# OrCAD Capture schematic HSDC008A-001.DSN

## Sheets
1 5. Hardware Page: title: TUSB1044EVM-008; rev: A; note: HSDC008-001
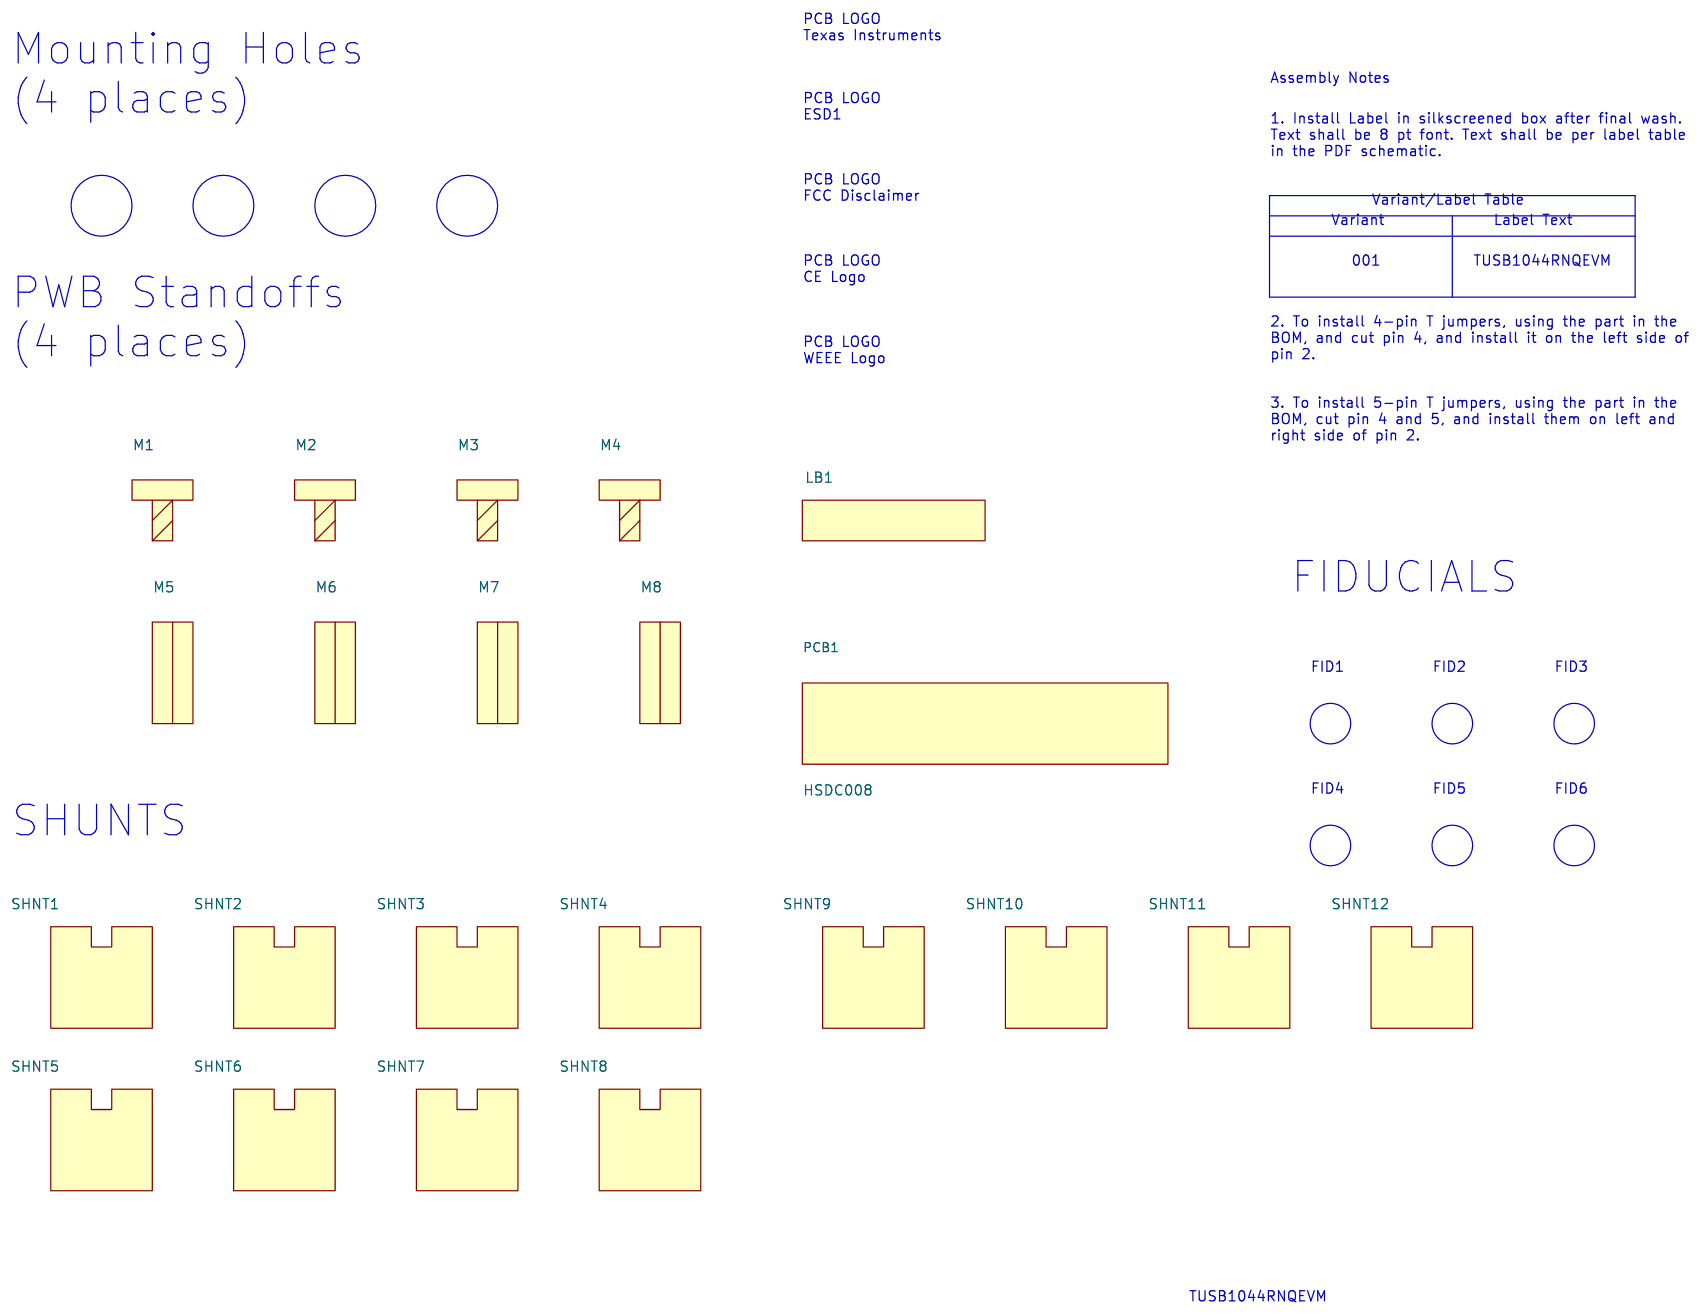
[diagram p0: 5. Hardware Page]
2 1. Block Diagram: title: TUSB1044RNQEVM
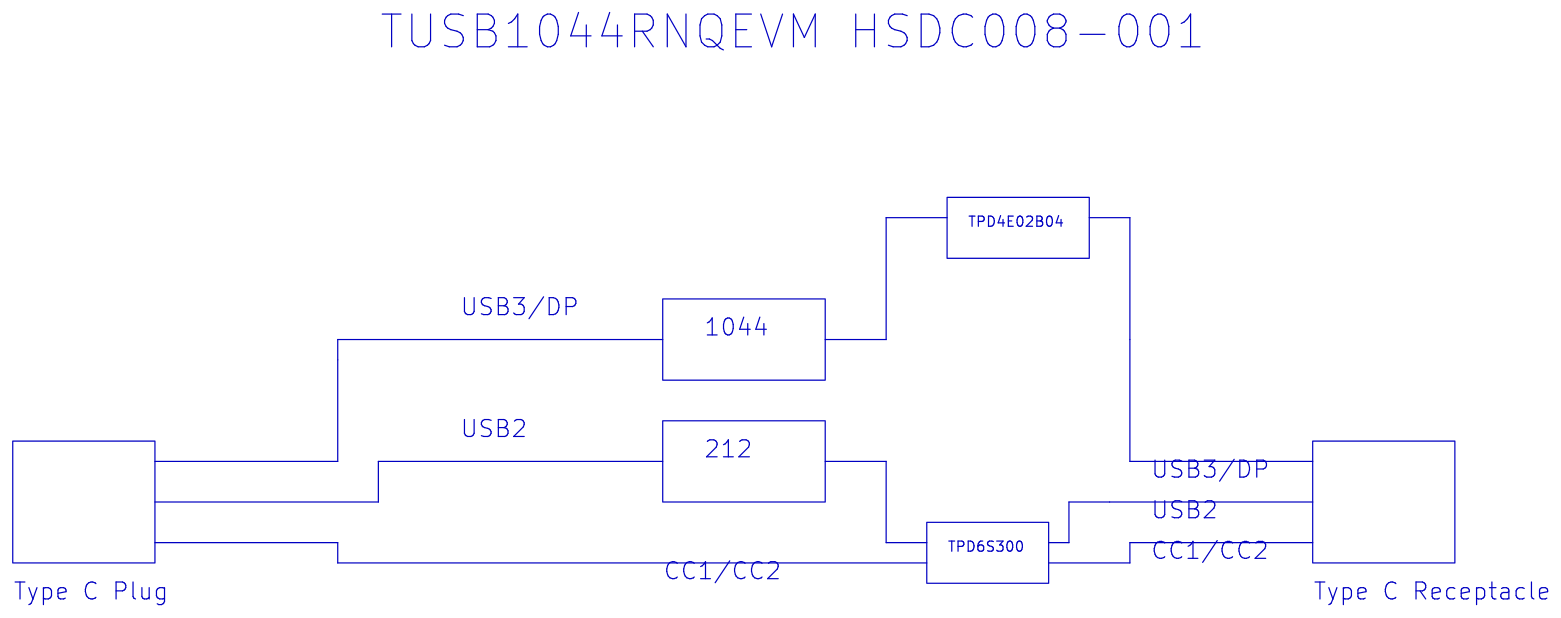
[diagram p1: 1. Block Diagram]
3 3. Configuration: size C; title: TUSB1044RNQEVM
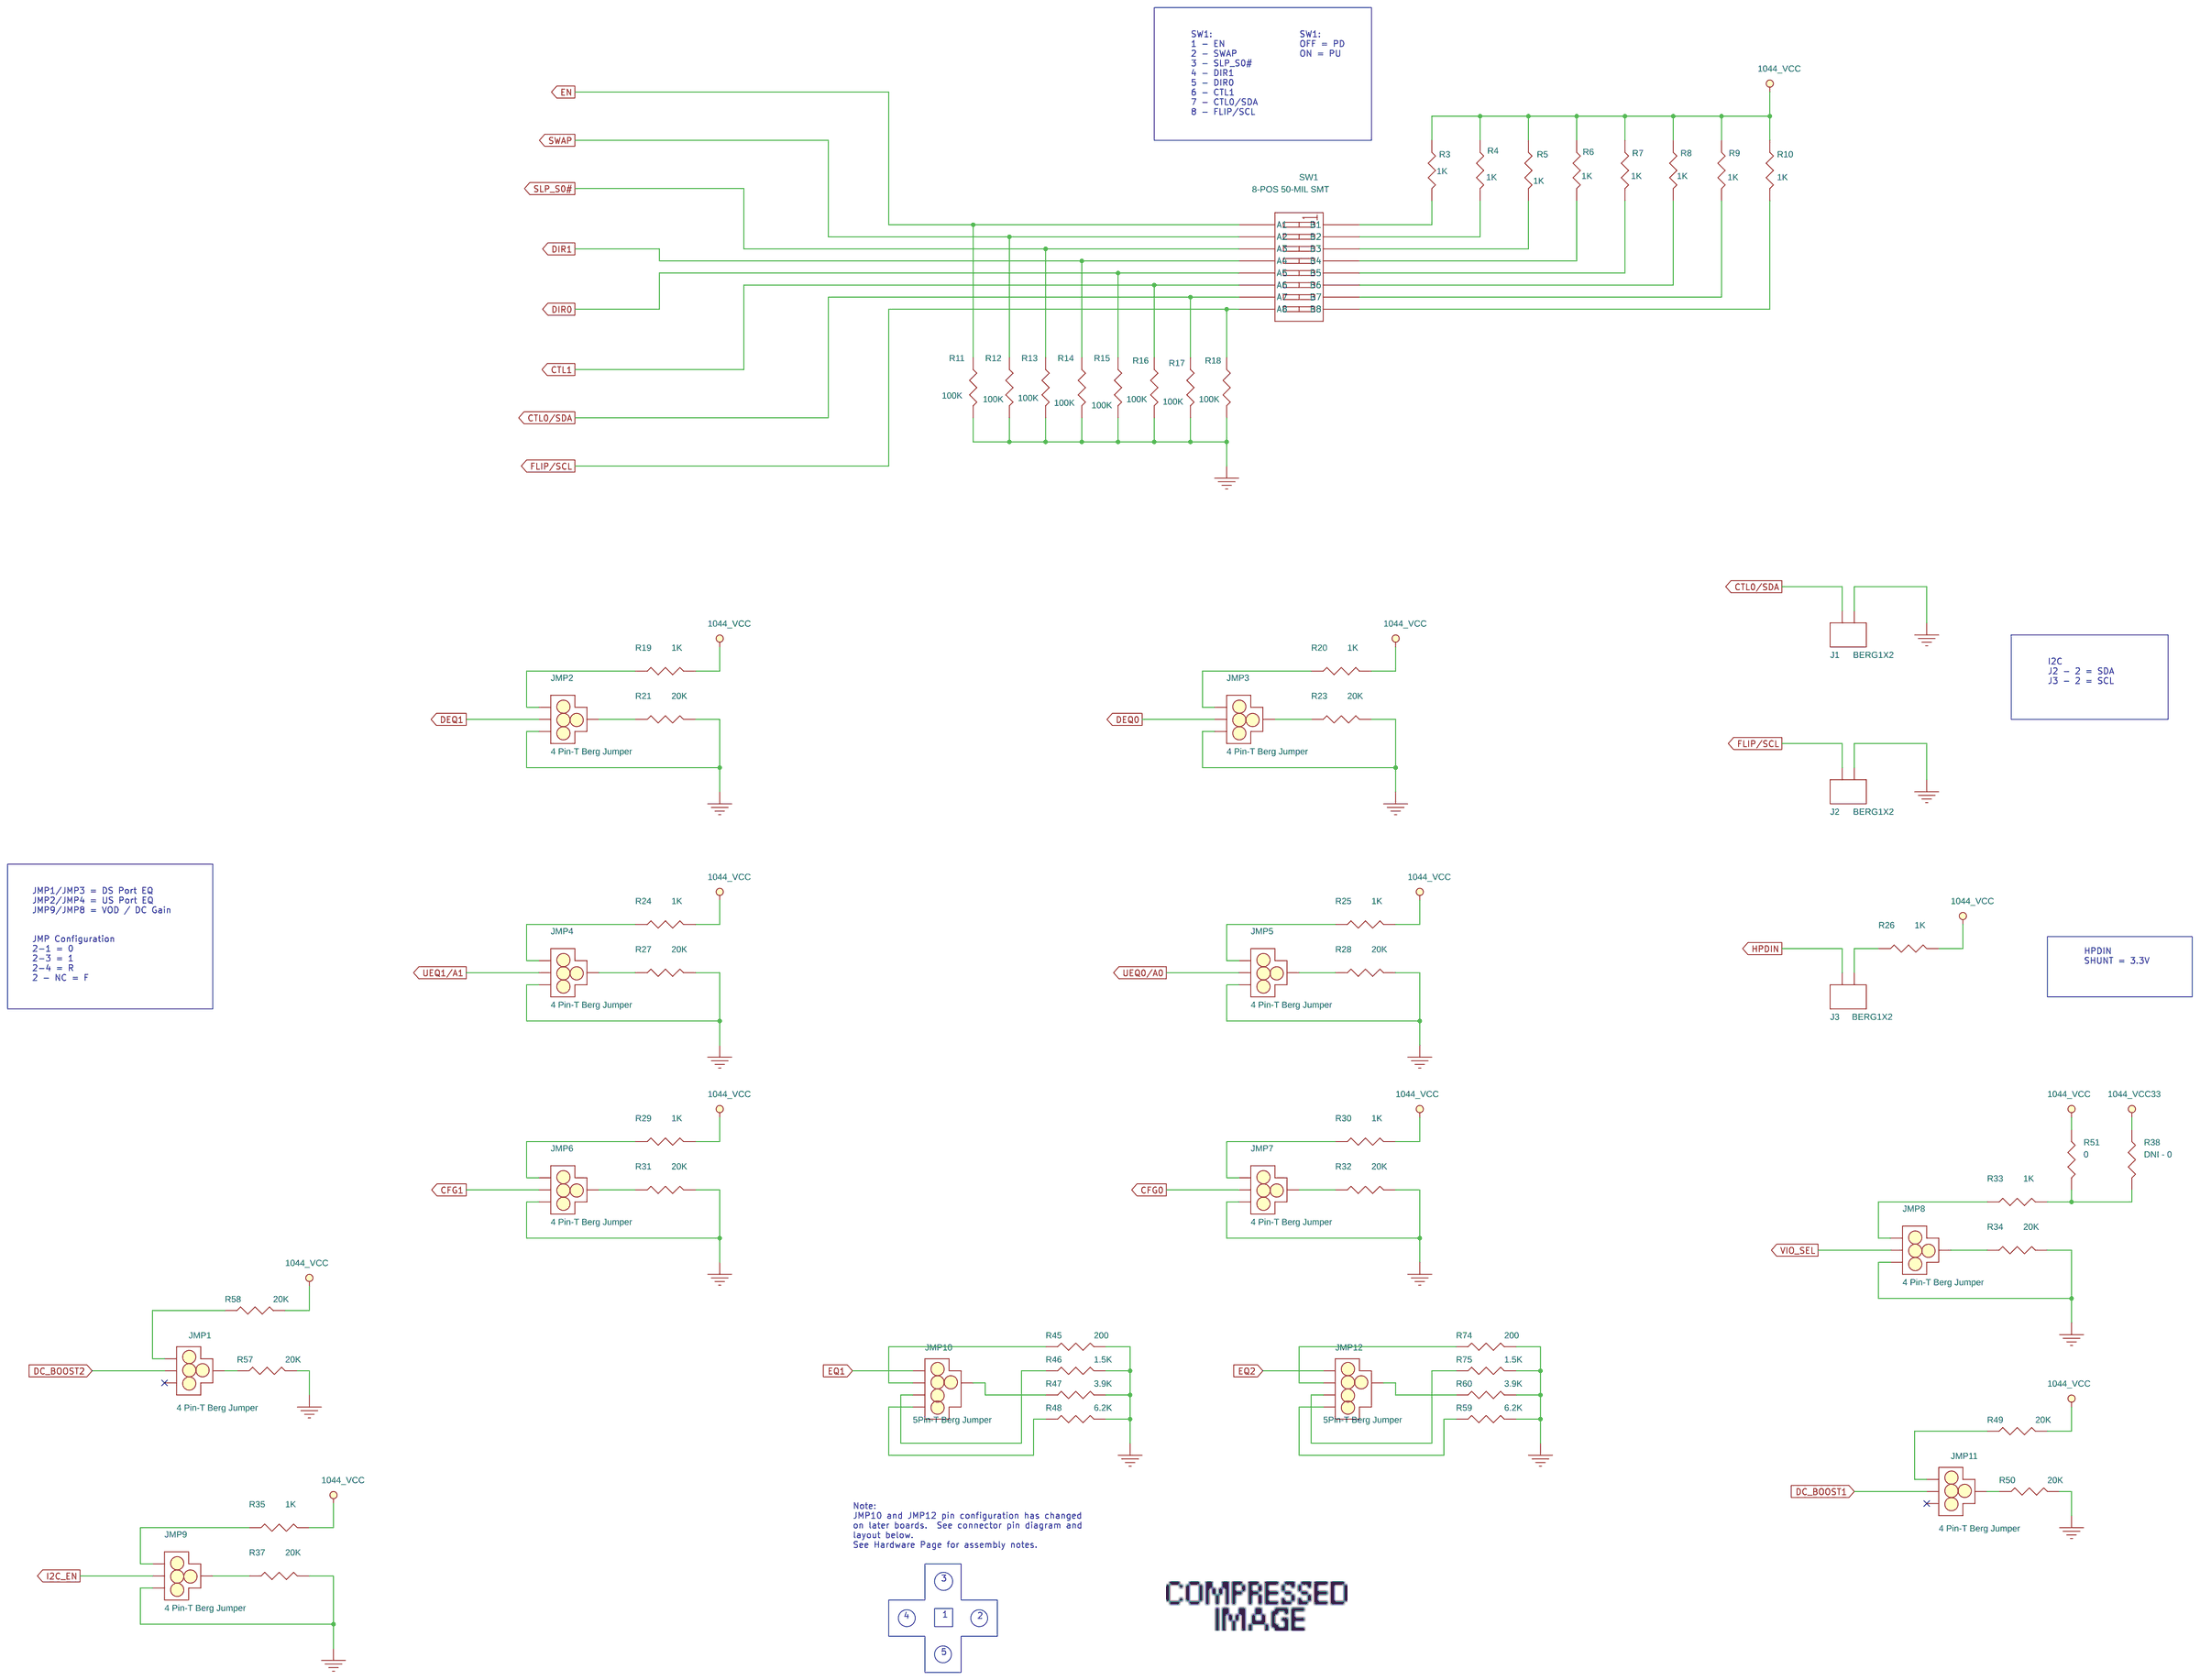
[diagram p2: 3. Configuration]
4 4. Power: size C; title: TUSB1044RNQEVM
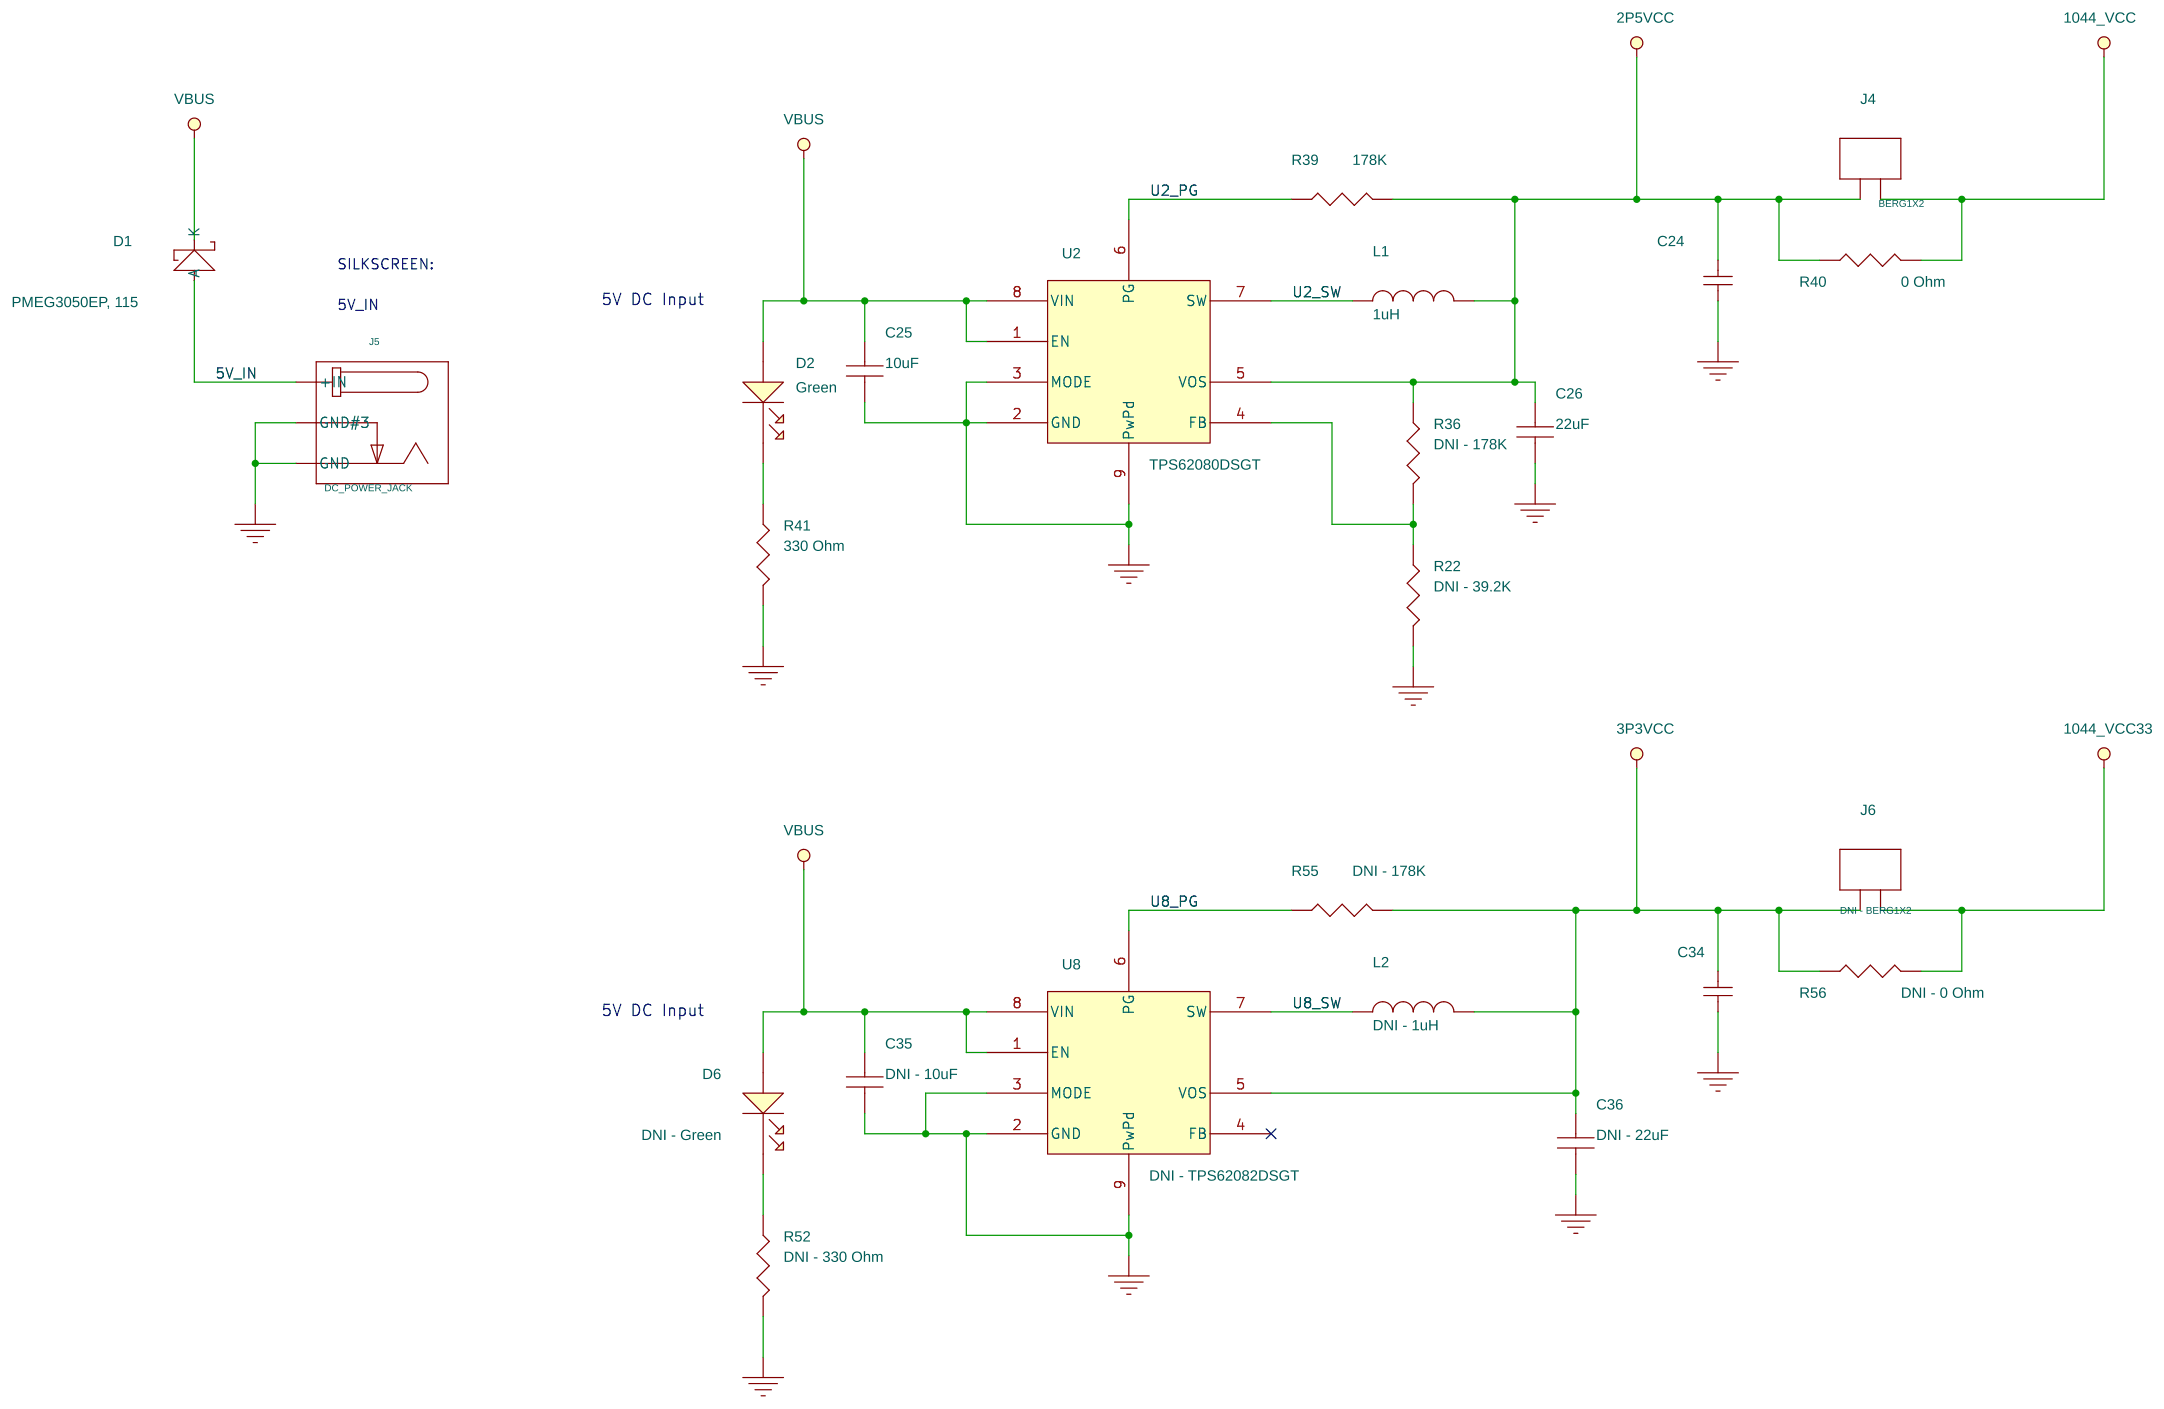
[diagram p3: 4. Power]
5 2. TUSB1044/46: size C; title: TUSB1044RNQEVM
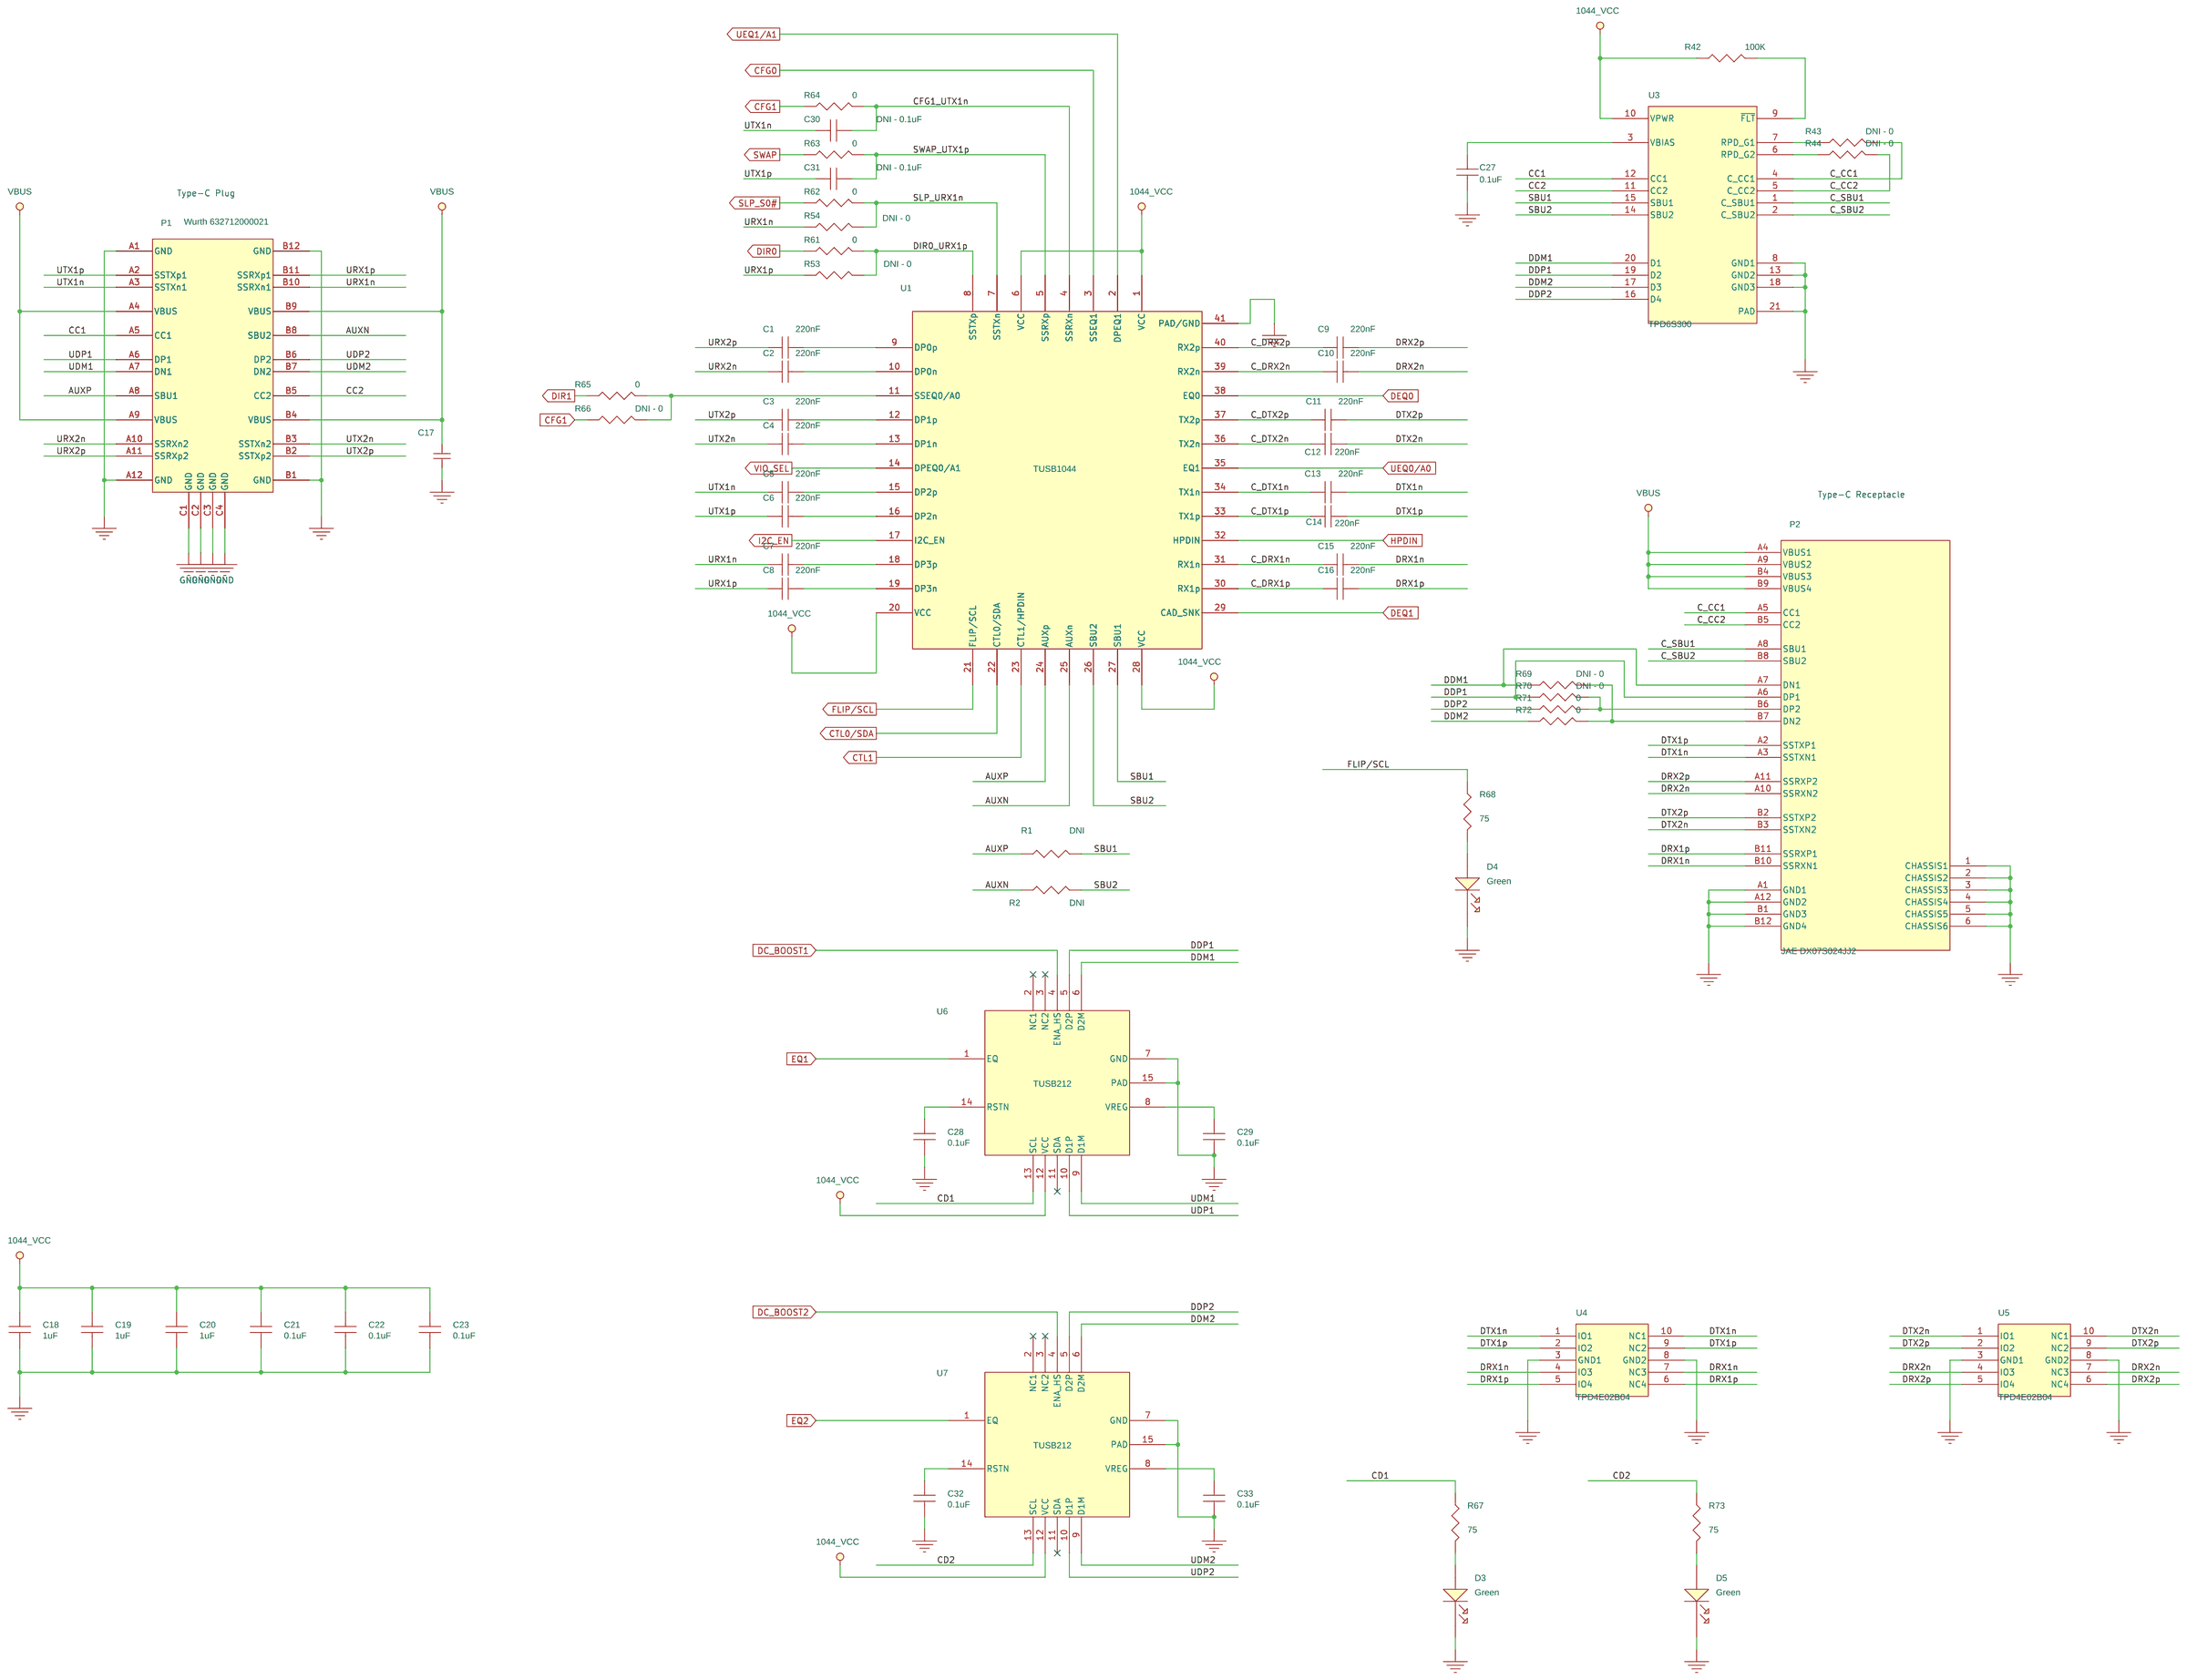
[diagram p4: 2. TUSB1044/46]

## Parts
sheet 2. TUSB1044/46
C1  220nF  [c0201]
C2  220nF  [c0201]
C3  220nF  [c0201]
C4  220nF  [c0201]
C5  220nF  [c0201]
C6  220nF  [c0201]
C7  220nF  [c0201]
C8  220nF  [c0201]
C9  220nF  [c0201]
C10  220nF  [c0201]
C11  220nF  [c0201]
C12  220nF  [c0201]
C13  220nF  [c0201]
C14  220nF  [c0201]
C15  220nF  [c0201]
C16  220nF  [c0201]
C17  10uF  [0805]
C18  1uF  [c0201]
C19  1uF  [c0201]
C20  1uF  [c0201]
C21  0.1uF  [c0201]
C22  0.1uF  [c0201]
C23  0.1uF  [c0201]
C27  0.1uF  [c0201]
C28  0.1uF  [c0201]
C29  0.1uF  [c0201]
C30  DNI - 0.1uF  [c0201]
C31  DNI - 0.1uF  [c0201]
C32  0.1uF  [c0201]
C33  0.1uF  [c0201]
D3  Green  [led0805]
D4  Green  [led0805]
D5  Green  [led0805]
P1  Wurth 632712000021  [usb-c_smrt_632_712_000_b6_b7]
P2  JAE DX07S024JJ2  [USB-C_SMRT_DX07S024JJ2]
R1  DNI  [r0402]
R2  DNI  [r0402]
R42  100K  [r0402]
R43  DNI - 0  [r0402]
R44  DNI - 0  [r0402]
R53  DNI - 0  [r0201]
R54  DNI - 0  [r0201]
R61  0  [r0201]
R62  0  [r0201]
R63  0  [r0201]
R64  0  [r0201]
R65  0  [r0201]
R66  DNI - 0  [r0201]
R67  75  [r0603]
R68  75  [r0603]
R69  DNI - 0  [r0201]
R70  DNI - 0  [r0201]
R71  0  [r0201]
R72  0  [r0201]
R73  75  [r0603]
U1  TUSB1044  [SKT_IRONWOOD_C14861_QFN-40]
U3  TPD6S300  [ruk0020b]
U4  TPD4E02B04  [dqa0010a]
U5  TPD4E02B04  [dqa0010a]
U6  TUSB212  [rgy_s-pvqfn-n14]
U7  TUSB212  [rgy_s-pvqfn-n14]
sheet 3. Configuration
J1  CON02  [HDR_THVT_1x2_100_M]
J2  CON02  [HDR_THVT_1x2_100_M]
J3  CON02  [HDR_THVT_1x2_100_M]
JMP1  4 Pin-T Berg Jumper  [berg2x3tee]
JMP2  4 Pin-T Berg Jumper  [berg2x3tee]
JMP3  4 Pin-T Berg Jumper  [berg2x3tee]
JMP4  4 Pin-T Berg Jumper  [berg2x3tee]
JMP5  4 Pin-T Berg Jumper  [berg2x3tee]
JMP6  4 Pin-T Berg Jumper  [berg2x3tee]
JMP7  4 Pin-T Berg Jumper  [berg2x3tee]
JMP8  4 Pin-T Berg Jumper  [berg2x3tee]
JMP9  4 Pin-T Berg Jumper  [berg2x3tee]
JMP10  5Pin-T Berg Jumper  [berg2x5tee]
JMP11  4 Pin-T Berg Jumper  [berg2x3tee]
JMP12  5Pin-T Berg Jumper  [berg2x5tee]
R3  1K  [r0402]
R4  1K  [r0402]
R5  1K  [r0402]
R6  1K  [r0402]
R7  1K  [r0402]
R8  1K  [r0402]
R9  1K  [r0402]
R10  1K  [r0402]
R11  100K  [r0402]
R12  100K  [r0402]
R13  100K  [r0402]
R14  100K  [r0402]
R15  100K  [r0402]
R16  100K  [r0402]
R17  100K  [r0402]
R18  100K  [r0402]
R19  1K  [r0402]
R20  1K  [r0402]
R21  20K  [r0402]
R23  20K  [r0402]
R24  1K  [r0402]
R25  1K  [r0402]
R26  1K  [r0402]
R27  20K  [r0402]
R28  20K  [r0402]
R29  1K  [r0402]
R30  1K  [r0402]
R31  20K  [r0402]
R32  20K  [r0402]
R33  1K  [r0402]
R34  20K  [r0402]
R35  1K  [r0402]
R37  20K  [r0402]
R38  DNI - 0  [r0402]
R45  200  [r0402]
R46  1.5K  [r0402]
R47  3.9K  [r0402]
R48  6.2K  [r0402]
R49  20K  [r0402]
R50  20K  [r0402]
R51  0  [r0402]
R57  20K  [r0402]
R58  20K  [r0402]
R59  6.2K  [r0402]
R60  3.9K  [r0402]
R74  200  [r0402]
R75  1.5K  [r0402]
SW1  8-POS 50-MIL SMT  [SW_SMVT_SPST_TDA08]
sheet 4. Power
C24  10uF  [0805]
C25  10uF  [0805]
C26  22uF  [0805]
C34  DNI - 10uF  [0805]
C35  DNI - 10uF  [0805]
C36  DNI - 22uF  [0805]
D1  SCHOTTKY  [diode_smb]
D2  Green  [led0805]
D6  DNI - Green  [led0805]
J4  CON02  [berg1x2]
J5  DC_PWR_JACK  [pj-202ah]
J6  CON02  [berg1x2]
L1  1uH  [IND_NR3015]
L2  DNI - 1uH  [IND_NR3015]
R22  DNI - 39.2K  [r0402]
R36  DNI - 178K  [r0402]
R39  178K  [r0402]
R40  0 Ohm  [r1206]
R41  330 Ohm  [r0603]
R52  DNI - 330 Ohm  [r0603]
R55  DNI - 178K  [r0402]
R56  DNI - 0 Ohm  [r1206]
U2  TPS62080DSGT  [dsg]
U8  DNI - TPS62082DSGT  [dsg]
sheet 5. Hardware Page
LB1  THD-47-478-10  [rectangle]
M1  NY PMS 440 005 PH  [screw]
M2  NY PMS 440 005 PH  [screw]
M3  NY PMS 440 005 PH  [screw]
M4  NY PMS 440 005 PH  [screw]
M5  1902E  [Standoff]
M6  1902E  [Standoff]
M7  1902E  [Standoff]
M8  1902E  [Standoff]
PCB1  HSDC008  [n/a]
SHNT1  QPC02SXGN-RC  [.1]
SHNT2  QPC02SXGN-RC  [.1]
SHNT3  QPC02SXGN-RC  [.1]
SHNT4  QPC02SXGN-RC  [.1]
SHNT5  QPC02SXGN-RC  [.1]
SHNT6  QPC02SXGN-RC  [.1]
SHNT7  QPC02SXGN-RC  [.1]
SHNT8  QPC02SXGN-RC  [.1]
SHNT9  QPC02SXGN-RC  [.1]
SHNT10  QPC02SXGN-RC  [.1]
SHNT11  QPC02SXGN-RC  [.1]
SHNT12  QPC02SXGN-RC  [.1]

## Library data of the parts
C1-C16 = cc0201
C17 C24 C34 = CAP: 6.3V Capacitor; $SEC: 1; ATIPartNo: 4210010600G; CDS_LIB: capacitor; DRAWING: @LIGHTNING_BOLT_NB_LIB.NOTE_BOOK(SCH_1):PAGE1; PHYS_PAGE: 1; ROT: 0; TOLERANCE: 10%; VER: 1; VOLTAGE: 6.3V; XY: (-9500,3550)
C18-C20 = cc0402: MFGP_N: GRM033R61A105ME15D
C21-C23 C27 C29 C33 = cc0402: MFGP_N: GRM033R62A104KE15D
C28 C30-C32 = cc0402
D2-D6 = Green_LED_2
P1 = Type_C_Plug_1
P2 = TypeC_JAE_TopMNT_1
R1-R21 R23-R35 R37 R39 R55 = r0402
R22 R36 R38 R42-R51 R53 R54 R57-R75 = R
U1 = TUSB1044RNQ_0
U3 = TPD8S300_0
U4 U5 = TPD4E02B04_0
U6 U7 = TUSB213_0
J1-J4 = CON02_2: Header; ATIPartNo: 6010014900G; CDS_LIB: connector; DEVICE_NAME: BERG1X2; DRAWING: @LIGHTNING_BOLT_NB_LIB.NOTE_BOOK(SCH_1):PAGE2; Digi-Key Part Number: 609-3507-ND; Manufacturer: FCI; Manufacturer Part Number: 68001-402HLF; Manufacturer's Part Number: 68001-402HLF; PHYS_PAGE: 2; ROT: 5; VER: 1; XY: (-6100,5150)
JMP1-JMP9 JMP11 = 4_Pin-T_Berg_Jumper
JMP10 JMP12 = 5Pin-T_Berg_Jumper
SW1 = SW_DIP-8_SM_0: Manuf: C&K(ITT-CANNON); Manuf PN: TDA08H0SK1R; Manufacturer: C&K(ITT-CANNON); Manufacturer Part Number: TDA08H0SK1R; Vendor: C&K (ITT-CANNON); Vendor Part Number: TDA08H0SK1R
C25 C26 C35 C36 = CAP_NP: 6.3V Capacitor
D1 = SCHOTTKY: Diode; $SEC: 1; CDS_LIB: diode; DEVICE_NAME: PMEG3050EP, 115; Digi-Key Part Number: 568-6753-2-ND; Manufacturer: NXP; Manufacturer Part Number: PMEG3050EP,115; Manufacturer's Part Number: PMEG3050EP,115; PHYS_PAGE: 1; ROT: 0; TOLERANCE: NA; VER: 1; VOLTAGE: 10V; XY: (-1750,3700)
J5 = 6140046600_DC_PWR_JACK: DC Power Jack; $SEC: 1; CDS_LIB: connector; DEVICE_NAME: DC_POWER_JACK; DRAWING: @LIGHTNING_BOLT_NB_LIB.NOTE_BOOK(SCH_1):PAGE2; Digi-Key Part Number: CP-202AH-ND; GroupName: COMMON; Manuf: CUI Inc.; Manuf PN: PJ-202AH; Manufacturer: CUI Inc.; Manufacturer Part Number: PJ-202AH; Manufacturer's Part Number: PJ-202AH; PHYS_PAGE: 2; ROT: 0; VER: 1; XY: (-4550,4450)
J6 = CON02_1: Header; ATIPartNo: 6010014900G; CDS_LIB: connector; DEVICE_NAME: DNI - BERG1X2; DRAWING: @LIGHTNING_BOLT_NB_LIB.NOTE_BOOK(SCH_1):PAGE2; Digi-Key Part Number: 609-3507-ND; Manufacturer: FCI; Manufacturer Part Number: 68001-402HLF; Manufacturer's Part Number: 68001-402HLF; PHYS_PAGE: 2; ROT: 5; VER: 1; XY: (-6100,5150)
L1 L2 = INDUCTOR: Inductor; CDS_LIB: Inductor; Digi-Key Part Number: 587-1647-1-ND; Manuf: Taiyo Yuden; Manuf PN: NR3015T1R0N; Manufacturer: Taiyo Yuden; Manufacturer Part Number: NR3015T1R0N; Manufacturer's Part Number: NR3015T1R0N
R40 R56 = r1206
R41 R52 = r0603
U2 U8 = TPS62082: DC/DC Converter; Digi-Key Part Number: 296-29647-1-ND; Manuf: Texas Instruments; Manuf PN: TPS62082DSGT; Manufacturer: Texas Instruments; Manufacturer Part Number: TPS62082DSGT; Manufacturer's Part Number: TPS62082DSGT
LB1 = Label
M1-M4 = Screw_40x.5_Nylon
M5-M8 = Standoff
PCB1 = PCB: Manufacturer: Any; Manufacturer Part Number: HSDC025
SHNT1-SHNT12 = Shunt

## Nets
5V_IN: D1.2(A) J5.1(+IN)
GND: C17.2(B) C18.2 C19.2 C20.2 C21.2 C22.2 C23.2 C24.2(B) C25.2 C26.2 C27.2 C28.2 C29.2 C32.2 C33.2 C34.2(B) C35.2 C36.2 D3.1(CATHODE) D4.1(CATHODE) D5.1(CATHODE) J1.1(P1) J2.1(P1) J5.2(GND) J5.3(GND#3) JMP2.1 JMP3.1 JMP4.1 JMP5.1 JMP6.1 JMP7.1 JMP8.1 JMP9.1 P1.A1(GND) P1.A12(GND) P1.B1(GND) P1.B12(GND) P1.C1(GND) P1.C2(GND) P1.C3(GND) P1.C4(GND) P2.1(CHASSIS1) P2.2(CHASSIS2) P2.3(CHASSIS3) P2.4(CHASSIS4) P2.5(CHASSIS5) P2.6(CHASSIS6) P2.A1(GND1) P2.A12(GND2) P2.B1(GND3) P2.B12(GND4) R11.2 R12.2 R13.2 R14.2 R15.2 R16.2 R17.2 R18.2 R21.2 R22.2 R23.2 R27.2 R28.2 R31.2 R32.2 R34.2 R37.2 R41.2 R45.2 R46.2 R47.2 R48.2 R50.2 R52.2 R57.2 R59.2 R60.2 R74.2 R75.2 U1.41(PAD/GND) U2.2(GND) U2.3(MODE) U2.9(PwPd) U3.8(GND1) U3.13(GND2) U3.18(GND3) U3.21(PAD) U4.3(GND1) U4.8(GND2) U5.3(GND1) U5.8(GND2) U6.7(GND) U6.15(PAD) U7.7(GND) U7.15(PAD) U8.2(GND) U8.3(MODE) U8.9(PwPd)
VBUS: C17.1(A) C25.1 C35.1 D1.1(K) D2.2(ANODE) D6.2(ANODE) P1.A4(VBUS) P1.A9(VBUS) P1.B4(VBUS) P1.B9(VBUS) P2.A4(VBUS1) P2.A9(VBUS2) P2.B4(VBUS3) P2.B9(VBUS4) U2.1(EN) U2.8(VIN) U8.1(EN) U8.8(VIN)
2P5VCC: C24.1(A) C26.1 J4.2(P2) L1.2 R36.1 R39.2 R40.1 U2.5(VOS)
3P3VCC: C34.1(A) C36.1 J6.1(P2) L2.2 R55.2 R56.1 U8.5(VOS)
1044_VCC: C18.1 C19.1 C20.1 C21.1 C22.1 C23.1 J4.1(P1) R3.1 R4.1 R5.1 R6.1 R7.1 R8.1 R9.1 R10.1 R19.2 R20.2 R24.2 R25.2 R26.2 R29.2 R30.2 R35.2 R40.2 R42.1 R49.2 R51.1 R58.2 U1.1(VCC) U1.6(VCC) U1.20(VCC) U1.28(VCC) U3.10(VPWR) U6.12(VCC) U7.12(VCC)
1044_VCC33: J6.2(P1) R38.1 R56.2
AUXN: P1.B8(SBU2) R2.1 U1.25(AUXn)
AUXP: P1.A8(SBU1) R1.1 U1.24(AUXp)
C_CC1: P2.A5(CC1) R43.2 U3.4(C_CC1)
C_CC2: P2.B5(CC2) R44.2 U3.5(C_CC2)
C_DRX1n: C15.1 U1.31(RX1n)
C_DRX1p: C16.1 U1.30(RX1p)
C_DRX2n: C10.1 U1.39(RX2n)
C_DRX2p: C9.1 U1.40(RX2p)
C_DTX1n: C13.1 U1.34(TX1n)
C_DTX1p: C14.1 U1.33(TX1p)
C_DTX2n: C12.1 U1.36(TX2n)
C_DTX2p: C11.1 U1.37(TX2p)
C_SBU1: P2.A8(SBU1) U3.1(C_SBU1)
C_SBU2: P2.B8(SBU2) U3.2(C_SBU2)
CC1: P1.A5(CC1) U3.12(CC1)
CC2: P1.B5(CC2) U3.11(CC2)
CD1: R67.1 U6.13(SCL)
CD2: R73.1 U7.13(SCL)
CFG0: JMP7.2 U1.3(SSEQ1)
CFG1: JMP6.2 R64.1 R66.1
CFG1_UTX1n: C30.2 R64.2 U1.4(SSRXn)
CTL0/SDA: J1.2(P2) R17.1 SW1.7(A7) U1.22(CTL0/SDA)
CTL1: R16.1 SW1.6(A6) U1.23(CTL1/HPDIN)
DC_BOOST1: JMP11.2 U6.4(ENA_HS)
DC_BOOST2: JMP1.2 U7.4(ENA_HS)
DDM1: P2.A7(DN1) R69.1 U3.20(D1) U6.6(D2M)
DDM2: R72.1 U3.17(D3) U7.6(D2M)
DDP1: P2.A6(DP1) R70.1 U3.19(D2) U6.5(D2P)
DDP2: R71.1 U3.16(D4) U7.5(D2P)
DEQ0: JMP3.2 U1.38(EQ0)
DEQ1: JMP2.2 U1.29(CAD_SNK)
DIR0: R15.1 R61.1 SW1.5(A5)
DIR0_URX1p: R53.2 R61.2 U1.8(SSTXp)
DIR1: R14.1 R65.1 SW1.4(A4)
DRX1n: C15.2 P2.B10(SSRXN1) U4.4(IO3) U4.7(NC3)
DRX1p: C16.2 P2.B11(SSRXP1) U4.5(IO4) U4.6(NC4)
DRX2n: C10.2 P2.A10(SSRXN2) U5.4(IO3) U5.7(NC3)
DRX2p: C9.2 P2.A11(SSRXP2) U5.5(IO4) U5.6(NC4)
DTX1n: C13.2 P2.A3(SSTXN1) U4.1(IO1) U4.10(NC1)
DTX1p: C14.2 P2.A2(SSTXP1) U4.2(IO2) U4.9(NC2)
DTX2n: C12.2 P2.B3(SSTXN2) U5.1(IO1) U5.10(NC1)
DTX2p: C11.2 P2.B2(SSTXP2) U5.2(IO2) U5.9(NC2)
EN: R11.1 SW1.1(A1)
EQ1: JMP10.1 U6.1(EQ)
EQ2: JMP12.1 U7.1(EQ)
FLIP/SCL: J2.2(P2) R18.1 R68.1 SW1.8(A8) U1.21(FLIP/SCL)
HPDIN: J3.2(P2) U1.32(HPDIN)
I2C_EN: JMP9.2 U1.17(I2C_EN)
SBU1: R1.2 U1.27(SBU1) U3.15(SBU1)
SBU2: R2.2 U1.26(SBU2) U3.14(SBU2)
SLP_S0#: R13.1 R62.1 SW1.3(A3)
SLP_URX1n: R54.2 R62.2 U1.7(SSTXn)
SWAP: R12.1 R63.1 SW1.2(A2)
SWAP_UTX1p: C31.2 R63.2 U1.5(SSRXp)
U2_PG: R39.1 U2.6(PG)
U2_SW: L1.1 U2.7(SW)
U8_PG: R55.1 U8.6(PG)
U8_SW: L2.1 U8.7(SW)
UDM1: P1.A7(DN1) U6.9(D1M)
UDM2: P1.B7(DN2) U7.9(D1M)
UDP1: P1.A6(DP1) U6.10(D1P)
UDP2: P1.B6(DP2) U7.10(D1P)
UEQ0/A0: JMP5.2 U1.35(EQ1)
UEQ1/A1: JMP4.2 U1.2(DPEQ1)
URX1n: C7.1 P1.B10(SSRXn1) R54.1
URX1p: C8.1 P1.B11(SSRXp1) R53.1
URX2n: C2.1 P1.A10(SSRXn2)
URX2p: C1.1 P1.A11(SSRXp2)
UTX1n: C5.1 C30.1 P1.A3(SSTXn1)
UTX1p: C6.1 C31.1 P1.A2(SSTXp1)
UTX2n: C4.1 P1.B3(SSTXn2)
UTX2p: C3.1 P1.B2(SSTXp2)
VIO_SEL: JMP8.2 U1.14(DPEQ0/A1)
N06058: R3.2 SW1.16(B1)
N06065: R4.2 SW1.15(B2)
N06072: R5.2 SW1.14(B3)
N06079: R6.2 SW1.13(B4)
N06086: R7.2 SW1.12(B5)
N06093: R8.2 SW1.11(B6)
N06100: R9.2 SW1.10(B7)
N06107: R10.2 SW1.9(B8)
N06374: JMP2.3 R19.1
N06386: JMP2.4 R21.1
N06671: JMP4.3 R24.1
N06683: JMP4.4 R27.1
N06999: JMP3.3 R20.1
N07011: JMP3.4 R23.1
N07344: JMP5.3 R25.1
N07356: JMP5.4 R28.1
N08045: R33.2 R38.2 R51.2
N08061: JMP8.3 R33.1
N08073: JMP8.4 R34.1
N08437: JMP9.3 R35.1
N08449: JMP9.4 R37.1
N08820: JMP7.3 R30.1
N08832: JMP7.4 R32.1
N09158: J3.1(P1) R26.1
N09488: JMP6.3 R29.1
N09500: JMP6.4 R31.1
N15413: D2.1(CATHODE) R41.1
N36817: JMP11.1 R49.1
N36900: JMP11.4 R50.1
N48828: C1.2 U1.9(DP0p)
N48832: C2.2 U1.10(DP0n)
N48836: C3.2 U1.12(DP1p)
N48840: C4.2 U1.13(DP1n)
N48844: C5.2 U1.15(DP2p)
N48848: C6.2 U1.16(DP2n)
N48852: C7.2 U1.18(DP3p)
N48856: C8.2 U1.19(DP3n)
N48872: P2.B6(DP2) R70.2 R71.2
N48884: P2.B7(DN2) R69.2 R72.2
N50484: R42.2 U3.9(~{FLT})
N50648: C27.1 U3.3(VBIAS)
N50826: R43.1 U3.7(RPD_G1)
N50830: R44.1 U3.6(RPD_G2)
N51380: C28.1 U6.14(RSTN)
N51484: C29.1 U6.8(VREG)
N69843: R65.2 R66.2 U1.11(SSEQ0/A0)
N74477: D3.2(ANODE) R67.2
N74875: D4.2(ANODE) R68.2
N79063: C32.1 U7.14(RSTN)
N79147: C33.1 U7.8(VREG)
N79572: D5.2(ANODE) R73.2
N80694: JMP1.1 R58.1
N80722: JMP1.4 R57.1
N151432: D6.1(CATHODE) R52.1
N157347: R22.1 R36.2 U2.4(FB)
N16784595: JMP10.2 R45.1
N16784603: JMP12.2 R74.1
N16784657: JMP10.3 R46.1
N16784667: JMP12.3 R75.1
N16784677: JMP10.4 R47.1
N16784691: JMP12.4 R60.1
N16784723: JMP10.5 R48.1
N16784735: JMP12.5 R59.1

Not connected (* = marked no-connect by the designer): JMP1 3*; JMP11 3*; U6 2(NC1)* 3(NC2)* 11(SDA)*; U7 2(NC1)* 3(NC2)* 11(SDA)*; U8 4(FB)*

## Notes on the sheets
sheet 1
- PCB LOGO
  Texas Instruments
- Mounting Holes
  (4 places)
- PCB LOGO
  ESD1
- Assembly Notes
- 1. Install Label in silkscreened box after final wash.
  Text shall be 8 pt font. Text shall be per label table
  in the PDF schematic.
- PCB LOGO
  FCC Disclaimer
- Variant/Label Table
- Variant
- Label Text
- PCB LOGO
  CE Logo
- 001
- TUSB1044RNQEVM
- PWB Standoffs
  (4 places)
- 2. To install 4-pin T jumpers, using the part in the
  BOM, and cut pin 4, and install it on the left side of
  pin 2.
- PCB LOGO
  WEEE Logo
- 3. To install 5-pin T jumpers, using the part in the
  BOM, cut pin 4 and 5, and install them on left and
  right side of pin 2.
- FIDUCIALS
- FID1
- FID2
- FID3
- FID4
- FID5
- FID6
- SHUNTS
- TUSB1044RNQEVM
sheet 2
- TUSB1044RNQEVM HSDC008-001
- TPD4E02B04
- USB3/DP
- 1044
- USB2
- 212
- USB3/DP
- USB2
- TPD6S300
- CC1/CC2
- Type C Plug
- CC1/CC2
- Type C Receptacle
sheet 3
- SW1:
  1 - EN
  2 - SWAP
  3 - SLP_S0#
  4 - DIR1
  5 - DIR0
  6 - CTL1
  7 - CTL0/SDA
  8 - FLIP/SCL
- SW1:
  OFF = PD
  ON = PU
- I2C
  J2 - 2 = SDA
  J3 - 2 = SCL
- JMP1/JMP3 = DS Port EQ
  JMP2/JMP4 = US Port EQ
  JMP9/JMP8 = VOD / DC Gain
- JMP Configuration
  2-1 = 0
  2-3 = 1
  2-4 = R
  2 - NC = F
- HPDIN
  SHUNT = 3.3V
- Note:
  JMP10 and JMP12 pin configuration has changed
  on later boards.  See connector pin diagram and
  layout below.
  See Hardware Page for assembly notes.
- 3
- 4
- 1
- 2
- 5
sheet 4
- SILKSCREEN:
- 5V_IN
- 5V DC Input
- 5V DC Input
sheet 5
- Type-C Plug
- Type-C Receptacle
